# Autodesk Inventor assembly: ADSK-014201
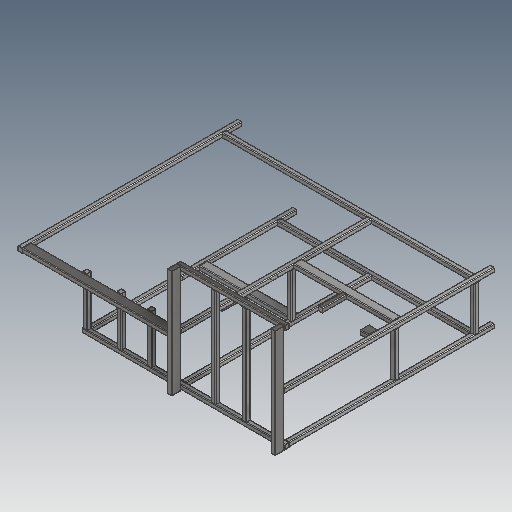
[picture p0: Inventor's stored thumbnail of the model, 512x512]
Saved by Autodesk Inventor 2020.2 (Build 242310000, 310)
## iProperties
_FrameDoc: Frame Assembly
_Version: 15.0.0
Part Number: ADSK-014201
Description: Phantom-Baugruppe
Document SubType Name: Baugruppe
Designer: lutzd
Mass: 236598 g
Surface Area: 119718 cm^2
Volume: 30619.1 cm^3
Density: 7.72715 g/cm^3
DocNumber: ADSK-014201
Folder: .
Dimensions: 1125x2290x2690 mm
Mass: 236,598 kg
Title: Gestellbaugruppen
Author: lutzd
Revision Number: -
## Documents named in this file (42)
- D:\07 - DEMODATEN\OTX 2019 - Dataset - UPDATE - Dez2019\Designs\07-Packing machine\ADSK-014200\Frame\ADSK-014201.iam
- D:\07 - DEMODATEN\OTX 2019 - Dataset - UPDATE - Dez2019\Designs\07-Packing machine\ADSK-014200\Frame\ADSK-014217.ipt
- D:\07 - DEMODATEN\OTX 2019 - Dataset - UPDATE - Dez2019\Designs\07-Packing machine\ADSK-014200\Frame\ADSK-014216.ipt
- D:\07 - DEMODATEN\OTX 2019 - Dataset - UPDATE - Dez2019\Designs\07-Packing machine\ADSK-014200\Frame\ADSK-014215.ipt
- D:\07 - DEMODATEN\OTX 2019 - Dataset - UPDATE - Dez2019\Designs\07-Packing machine\ADSK-014200\Frame\ADSK-014214.ipt
- D:\07 - DEMODATEN\OTX 2019 - Dataset - UPDATE - Dez2019\Designs\07-Packing machine\ADSK-014200\Frame\ADSK-014213.ipt
- D:\07 - DEMODATEN\OTX 2019 - Dataset - UPDATE - Dez2019\Designs\07-Packing machine\ADSK-014200\Frame\ADSK-014212.ipt
- D:\07 - DEMODATEN\OTX 2019 - Dataset - UPDATE - Dez2019\Designs\07-Packing machine\ADSK-014200\Frame\ADSK-014211.ipt
- D:\07 - DEMODATEN\OTX 2019 - Dataset - UPDATE - Dez2019\Designs\07-Packing machine\ADSK-014200\Frame\ADSK-014210.ipt
- D:\07 - DEMODATEN\OTX 2019 - Dataset - UPDATE - Dez2019\Designs\07-Packing machine\ADSK-014200\Frame\ADSK-014209.ipt
- D:\07 - DEMODATEN\OTX 2019 - Dataset - UPDATE - Dez2019\Designs\07-Packing machine\ADSK-014200\Frame\ADSK-014208.ipt
- D:\07 - DEMODATEN\OTX 2019 - Dataset - UPDATE - Dez2019\Designs\07-Packing machine\ADSK-014200\Frame\ADSK-014207.ipt
- D:\07 - DEMODATEN\OTX 2019 - Dataset - UPDATE - Dez2019\Designs\07-Packing machine\ADSK-014200\Frame\ADSK-014206.ipt
- D:\07 - DEMODATEN\OTX 2019 - Dataset - UPDATE - Dez2019\Designs\07-Packing machine\ADSK-014200\Frame\ADSK-014204.ipt
- D:\07 - DEMODATEN\OTX 2019 - Dataset - UPDATE - Dez2019\Designs\07-Packing machine\ADSK-014200\Frame\ADSK-014203.ipt
- D:\07 - DEMODATEN\OTX 2019 - Dataset - UPDATE - Dez2019\Designs\07-Packing machine\ADSK-014200\Frame\ADSK-014202.ipt
- D:\07 - DEMODATEN\OTX 2019 - Dataset - UPDATE - Dez2019\Designs\07-Packing machine\ADSK-014200\Frame\ADSK-014220.ipt
- D:\07 - DEMODATEN\OTX 2019 - Dataset - UPDATE - Dez2019\Designs\07-Packing machine\ADSK-014200\Frame\ADSK-014219.ipt
- D:\07 - DEMODATEN\OTX 2019 - Dataset - UPDATE - Dez2019\Designs\07-Packing machine\ADSK-014200\Frame\ADSK-014223.ipt
- D:\07 - DEMODATEN\OTX 2019 - Dataset - UPDATE - Dez2019\Designs\07-Packing machine\ADSK-014200\Frame\ADSK-014222.ipt
- D:\07 - DEMODATEN\OTX 2019 - Dataset - UPDATE - Dez2019\Designs\07-Packing machine\ADSK-014200\Frame\ADSK-014221.ipt
- D:\07 - DEMODATEN\OTX 2019 - Dataset - UPDATE - Dez2019\Designs\07-Packing machine\ADSK-014200\Frame\ADSK-014234.ipt
- D:\07 - DEMODATEN\OTX 2019 - Dataset - UPDATE - Dez2019\Designs\07-Packing machine\ADSK-014200\Frame\ADSK-014233.ipt
- D:\07 - DEMODATEN\OTX 2019 - Dataset - UPDATE - Dez2019\Designs\07-Packing machine\ADSK-014200\Frame\ADSK-014232.ipt
- D:\07 - DEMODATEN\OTX 2019 - Dataset - UPDATE - Dez2019\Designs\07-Packing machine\ADSK-014200\Frame\ADSK-014231.ipt
- D:\07 - DEMODATEN\OTX 2019 - Dataset - UPDATE - Dez2019\Designs\07-Packing machine\ADSK-014200\Frame\ADSK-014227.ipt
- D:\07 - DEMODATEN\OTX 2019 - Dataset - UPDATE - Dez2019\Designs\07-Packing machine\ADSK-014200\Frame\ADSK-014226.ipt
- D:\07 - DEMODATEN\OTX 2019 - Dataset - UPDATE - Dez2019\Designs\07-Packing machine\ADSK-014200\Frame\ADSK-014225.ipt
- D:\07 - DEMODATEN\OTX 2019 - Dataset - UPDATE - Dez2019\Designs\07-Packing machine\ADSK-014200\Frame\ADSK-014238.ipt
- D:\07 - DEMODATEN\OTX 2019 - Dataset - UPDATE - Dez2019\Designs\07-Packing machine\ADSK-014200\Frame\ADSK-014239.ipt
- D:\07 - DEMODATEN\OTX 2019 - Dataset - UPDATE - Dez2019\Designs\07-Packing machine\ADSK-014200\Frame\ADSK-014240.ipt
- D:\07 - DEMODATEN\OTX 2019 - Dataset - UPDATE - Dez2019\Designs\07-Packing machine\ADSK-014200\Frame\ADSK-014241.ipt
- D:\07 - DEMODATEN\OTX 2019 - Dataset - UPDATE - Dez2019\Designs\07-Packing machine\ADSK-014200\Frame\ADSK-014253.ipt
- D:\07 - DEMODATEN\OTX 2019 - Dataset - UPDATE - Dez2019\Designs\07-Packing machine\ADSK-014200\Frame\ADSK-014252.ipt
- D:\07 - DEMODATEN\OTX 2019 - Dataset - UPDATE - Dez2019\Designs\07-Packing machine\ADSK-014200\Frame\ADSK-014251.ipt
- D:\07 - DEMODATEN\OTX 2019 - Dataset - UPDATE - Dez2019\Designs\07-Packing machine\ADSK-014200\Frame\ADSK-014250.ipt
- D:\07 - DEMODATEN\OTX 2019 - Dataset - UPDATE - Dez2019\Designs\07-Packing machine\ADSK-014200\Frame\ADSK-014259.ipt
- D:\07 - DEMODATEN\OTX 2019 - Dataset - UPDATE - Dez2019\Designs\07-Packing machine\ADSK-014200\Frame\ADSK-014258.ipt
- D:\07 - DEMODATEN\OTX 2019 - Dataset - UPDATE - Dez2019\Designs\07-Packing machine\ADSK-014200\Frame\ADSK-014257.ipt
- D:\07 - DEMODATEN\OTX 2019 - Dataset - UPDATE - Dez2019\Designs\07-Packing machine\ADSK-014200\Frame\ADSK-014256.ipt
- D:\07 - DEMODATEN\OTX 2019 - Dataset - UPDATE - Dez2019\Designs\07-Packing machine\ADSK-014200\Frame\ADSK-014255.ipt
- D:\07 - DEMODATEN\OTX 2019 - Dataset - UPDATE - Dez2019\Designs\07-Packing machine\ADSK-014200\Frame\ADSK-014254.ipt
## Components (42 placed, 6 different names)
1. Gestellreferenzmodell
2. DIN 50 x 50 x 5:1
3. DIN 50 x 50 x 5:2
4. DIN 50 x 50 x 5:3
5. DIN 50 x 50 x 5:4
6. DIN 50 x 50 x 5:5
7. DIN 50 x 50 x 5:6
8. DIN 50 x 50 x 5:7
9. DIN 50 x 50 x 5:8
10. DIN 50 x 50 x 5:9
11. DIN 50 x 50 x 5:10
12. DIN 50 x 50 x 5:11
13. DIN 50 x 50 x 5:13
14. DIN 50 x 50 x 5:14
15. DIN 50 x 50 x 5:15
16. DIN 50 x 50 x 5:16
17. DIN 50 x 50 x 5:17
18. DIN 50 x 50 x 5:18
19. DIN 90 x 50 x 5:1
20. DIN 90 x 50 x 5:2
21. Gerundete Ecken (mm) 5 x 39,384472 x 39,384472:1
22. Gerundete Ecken (mm) 5 x 39,384472 x 39,384472:2
23. Gerundete Ecken (mm) 5 x 39,384472 x 39,384472:3
24. Gerundete Ecken (mm) 5 x 39,384472 x 39,384472:4
25. Gerundete Ecken (mm) 5 x 39,384472 x 39,384472:7
26. Gerundete Ecken (mm) 5 x 39,384472 x 39,384472:8
27. Gerundete Ecken (mm) 5 x 39,384472 x 39,384472:9
28. Gerundete Ecken (mm) 5 x 39,384472 x 39,384472:10
29. DIN 100 x 50 x 5:2
30. Gerundete Ecken (mm) 5 x 39,384472 x 39,384472:11
31. DIN 100 x 50 x 5:3
32. DIN 100 x 50 x 5:4
33. DIN 50 x 50 x 5:21
34. DIN 100 x 50 x 5:5
35. Gerundete Ecken (mm) 5 x 89,384472 x 39,384472:1
36. Gerundete Ecken (mm) 5 x 89,384472 x 39,384472:2
37. Gerundete Ecken (mm) 5 x 39,384472 x 39,384472:12
38. Gerundete Ecken (mm) 5 x 39,384472 x 39,384472:13
39. Gerundete Ecken (mm) 5 x 89,384472 x 39,384472:3
40. Gerundete Ecken (mm) 5 x 89,384472 x 39,384472:4
41. DIN 50 x 50 x 5:19
42. DIN 50 x 50 x 5:20
